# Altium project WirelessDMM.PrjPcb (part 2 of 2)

## Sheet WirelessDMM_AFE.SchDoc: AFE
size 431 x 279 mm; Date: Not shown in title block; ApprovedBy: Not shown in title block; CheckedBy: Not shown in title block; Author: Not shown in title block; CompanyName: Not shown in title block; DrawnBy: Victor Salomon; Engineer: Not shown in title block; Organization: Not shown in title block; Address1: Not shown in title block; Address2: Not shown in title block; Address3: Not shown in title block; Address4: Not shown in title block; DocumentNumber: 3; Revision: Use project parameter SCH_Rev; SheetNumber: 3; SheetTotal: 5; PageSetup: Record=PageOptions¦CenterHorizontal=True¦CenterVertical=True¦PrintScale=1.00¦XCorrection=1.00¦YCorrection=1.00¦PrintKind=0¦BorderSize=5000000¦LeftOffset=0¦BottomOffset=0¦Orientation=2¦PaperLength=1000¦PaperWidth=1000¦Scale=100¦PaperSource=15¦PrintQuality=600¦MediaType=1¦DitherType=10¦PaperKind=Letter¦PrintScaleMode=1
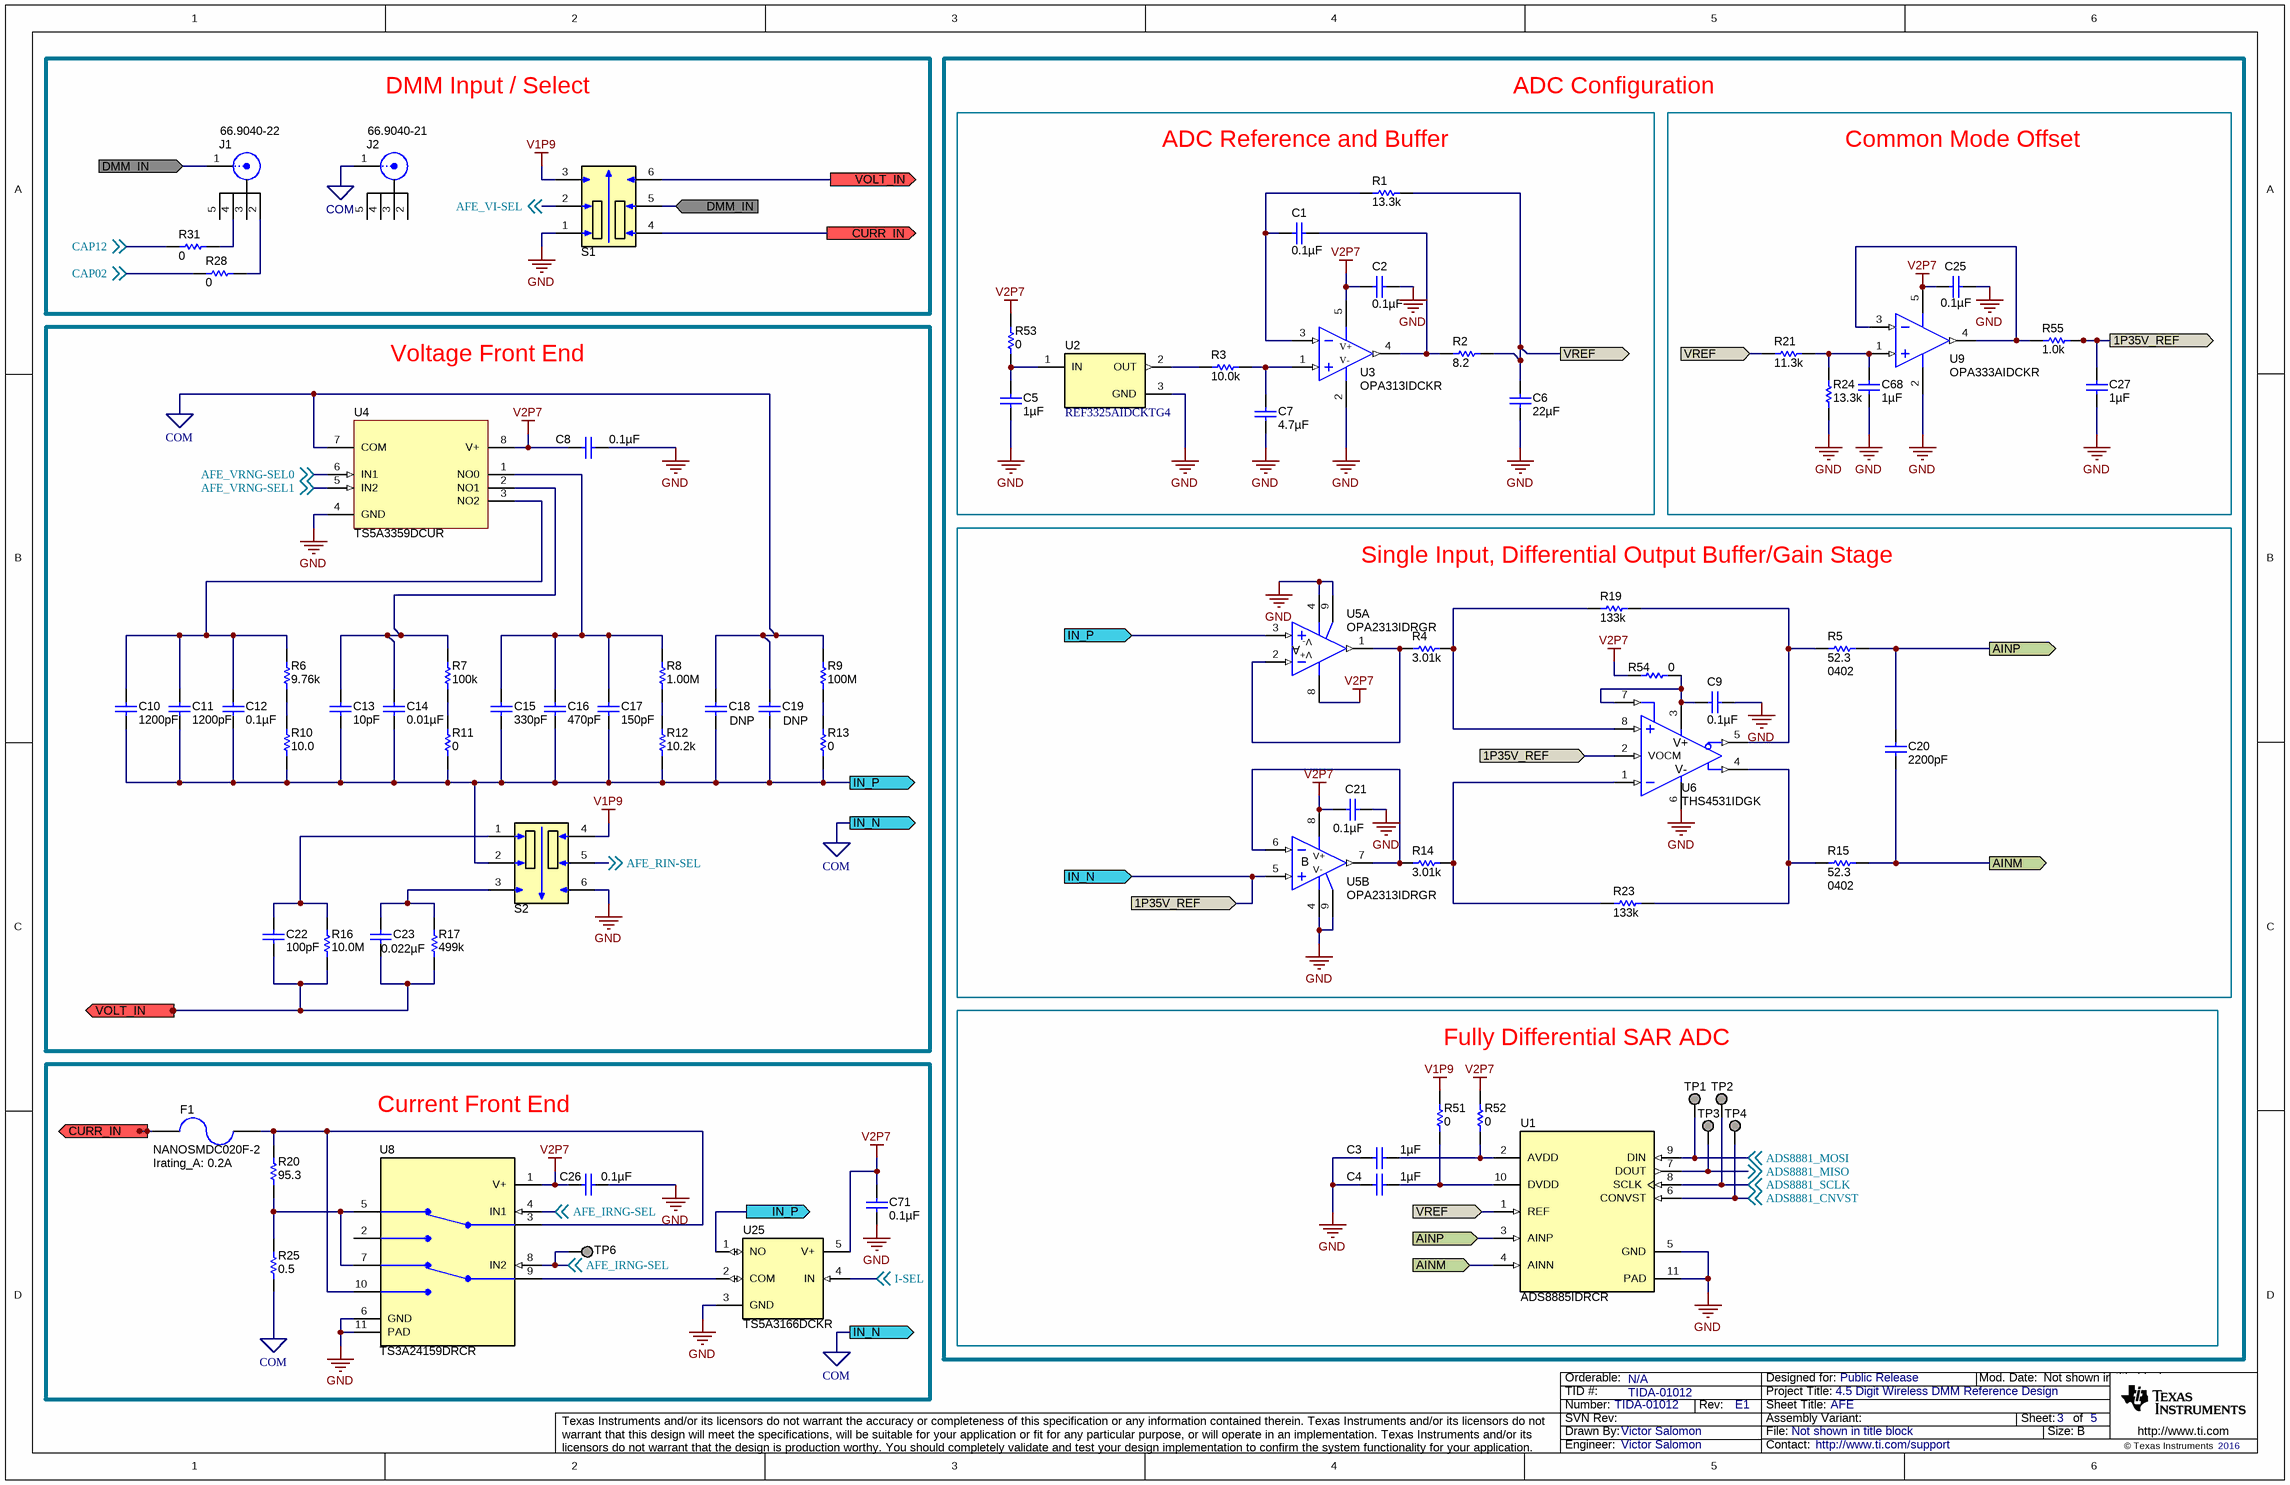
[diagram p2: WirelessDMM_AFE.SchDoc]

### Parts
C1  ValueDisplayed: 0.1µF  [0402S]  (hidden comment: GRM155R71C104JA88D)
C2  ValueDisplayed: 0.1µF  [0201]  (hidden comment: CL03A104KP3NNNC)
C3  ValueDisplayed: 1µF  [0402S]  (hidden comment: GRM155R61A105KE15D)
C4  ValueDisplayed: 1µF  [0402S]  (hidden comment: GRM155R61A105KE15D)
C5  ValueDisplayed: 1µF  [0402S]  (hidden comment: C1005X5R0J105M050BB)
C6  ValueDisplayed: 22µF  [0402S]  (hidden comment: GRM155R60J226ME11D)
C7  ValueDisplayed: 4.7µF  [0603S]  (hidden comment: GRM188R6YA475KE15D)
C8  ValueDisplayed: 0.1µF  [0201]  (hidden comment: CL03A104KP3NNNC)
C9  ValueDisplayed: 0.1µF  [0201]  (hidden comment: CL03A104KP3NNNC)
C10  ValueDisplayed: 1200pF  [0402S]  (hidden comment: C0402C122J5GACTU)
C11  ValueDisplayed: 1200pF  [0402S]  (hidden comment: C0402C122J5GACTU)
C12  ValueDisplayed: 0.1µF  [0603S]  (hidden comment: C0603C104J5RACTU)
C13  ValueDisplayed: 10pF  [0603S]  (hidden comment: C0603C100F5GAC7867)
C14  ValueDisplayed: 0.01µF  [0805_HV1]  (hidden comment: C0805C103F1GACTU)
C15  ValueDisplayed: 330pF  [0402S]  (hidden comment: GRM1555C1H331FA01J)
C16  ValueDisplayed: 470pF  [0805_HV1]  (hidden comment: 08055A471FAT2A)
C17  ValueDisplayed: 150pF  [0402S]  (hidden comment: GRM1555C1H151JA01D)
C18  value DNP  [0402]  (hidden comment: Used in BOM report)
C19  value DNP  [0402]  (hidden comment: Used in BOM report)
C20  ValueDisplayed: 2200pF  [0603S]  (hidden comment: GRM1885C1H222JA01D)
C21  ValueDisplayed: 0.1µF  [0201]  (hidden comment: CL03A104KP3NNNC)
C22  ValueDisplayed: 100pF  [0603S]  (hidden comment: C1608C0G2A101F080AA)
C23  ValueDisplayed: 0.022µF  [0603S]  (hidden comment: C1608X7R2A223K)
C25  ValueDisplayed: 0.1µF  [0201]  (hidden comment: CL03A104KP3NNNC)
C26  ValueDisplayed: 0.1µF  [0201]  (hidden comment: CL03A104KP3NNNC)
C27  ValueDisplayed: 1µF  [0402S]  (hidden comment: C1005X5R0J105M050BB)
C68  ValueDisplayed: 1µF  [0402S]  (hidden comment: C1005X5R0J105M050BB)
C71  ValueDisplayed: 0.1µF  [0201]  (hidden comment: CL03A104KP3NNNC)
F1  NANOSMDC020F-2  Irating_A: 0.2A  [FUSE_NANO02]
J1  66.9040-22  [Multi-Contact_66_9040-22]
J2  66.9040-21  [Multi-Contact_66_9040-21]
R1  ValueDisplayed: 13.3k  [0402S]  (hidden comment: CRCW040213K3FKED)
R2  ValueDisplayed: 8.2  [0402S]  (hidden comment: CRCW04028R20JNED)
R3  ValueDisplayed: 10.0k  [0402S]  (hidden comment: CRCW040210K0FKED)
R4  ValueDisplayed: 3.01k  [0402S]  (hidden comment: CRCW04023K01FKED)
R5  ValueDisplayed: 52.3  PackageReference: 0402  [0402S]  (hidden comment: CRCW040252R3FKED)
R6  ValueDisplayed: 9.76k  [0402S]  (hidden comment: CRCW04029K76FKED)
R7  ValueDisplayed: 100k  [0402S]  (hidden comment: RG1005P-104-B-T5)
R8  ValueDisplayed: 1.00M  [0402S]  (hidden comment: CRCW04021M00FKED)
R9  ValueDisplayed: 100M  [0603S]  (hidden comment: CRCW0603100MJPEAHR)
R10  ValueDisplayed: 10.0  [0402S]  (hidden comment: CRCW040210R0FKED)
R11  ValueDisplayed: 0  [0402S]  (hidden comment: CRCW04020000Z0ED)
R12  ValueDisplayed: 10.2k  [0402S]  (hidden comment: CRCW040210K2FKED)
R13  ValueDisplayed: 0  [0402S]  (hidden comment: CRCW04020000Z0ED)
R14  ValueDisplayed: 3.01k  [0402S]  (hidden comment: CRCW04023K01FKED)
R15  ValueDisplayed: 52.3  PackageReference: 0402  [0402S]  (hidden comment: CRCW040252R3FKED)
R16  ValueDisplayed: 10.0M  [1206L]  (hidden comment: CRHV1206AF10M0FKE5)
R17  ValueDisplayed: 499k  [0402S]  (hidden comment: CRCW0402499KFKED)
R19  ValueDisplayed: 133k  [0402S]  (hidden comment: CRCW0402133KFKED)
R20  ValueDisplayed: 95.3  [2512L]  (hidden comment: CRCW251295R3FKEG)
R21  ValueDisplayed: 11.3k  [0402S]  (hidden comment: CRCW040211K3FKED)
R23  ValueDisplayed: 133k  [0402S]  (hidden comment: CRCW0402133KFKED)
R24  ValueDisplayed: 13.3k  [0402S]  (hidden comment: CRCW040213K3FKED)
R25  ValueDisplayed: 0.5  [0603]  (hidden comment: RL0603FR-070R5L)
R28  ValueDisplayed: 0  [0402S]  (hidden comment: MCR01MZPJ000)
R31  ValueDisplayed: 0  [0402S]  (hidden comment: MCR01MZPJ000)
R51  ValueDisplayed: 0  [0402S]  (hidden comment: MCR01MZPJ000)
R52  ValueDisplayed: 0  [0402S]  (hidden comment: MCR01MZPJ000)
R53  ValueDisplayed: 0  [0402S]  (hidden comment: MCR01MZPJ000)
R54  ValueDisplayed: 0  [0402S]  (hidden comment: MCR01MZPJ000)
R55  ValueDisplayed: 1.0k  [0402S]  (hidden comment: CRCW04021K00JNED)
S1  GS-113-0043  [SW_GS-113-0043]  (value not drawn)
S2  GS-113-0043  [SW_GS-113-0043]  (value not drawn)
TP1  TESTPOINT  [TP_SM_1MM]  (value not drawn)  (no BOM)
TP2  TESTPOINT  [TP_SM_1MM]  (value not drawn)  (no BOM)
TP3  TESTPOINT  [TP_SM_1MM]  (value not drawn)  (no BOM)
TP4  TESTPOINT  [TP_SM_1MM]  (value not drawn)  (no BOM)
TP6  TESTPOINT  [TP_SM_1MM]  (value not drawn)  (no BOM)
U1  ADS8885IDRCR  [DRC0010D]
U2  REF3325AIDCKTG4  [DCK0003A_N]
U3  OPA313IDCKR  [DCK0005A_N]
U4  TS5A3359DCUR  [DCU0008A_N]
U5  OPA2313IDRGR  [DRG0008A]  (parts A,B of 2)
U6  THS4531IDGK  [DGK0008A_N]
U8  TS3A24159DRCR  [DRC0010J]
U9  OPA333AIDCKR  [DCK0005A_N]
U25  TS5A3166DCKR  [DCK0005A_N]

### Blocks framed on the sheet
DMM Input / Select: J1 J2 R28 R31 S1
ADC Reference and Buffer: C1 C2 C5-C7 R1-R3 R53 U2 U3
Common Mode Offset: C25 C27 C68 R21 R24 R55 U9
Voltage Front End: C8 C10-C19 C22 C23 R6-R13 R16 R17 S2 U4
Single Input, Differential Output Buffer/Gain Stage: C9 C20 C21 R4 R5 R14 R15 R19 R23 R54 U5 U6
Fully Differential SAR ADC: C3 C4 R51 R52 TP1-TP4 U1
Current Front End: C26 C71 F1 R20 R25 TP6 U8 U25

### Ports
1P35V_REF (in), 1P35V_REF (out), AINM (in), AINM (out), AINP (in), AINP (out), CURR_IN (in), CURR_IN (out), DMM_IN (in), IN_N (in), IN_N (out), IN_P (in), IN_P (out), VOLT_IN (in), VOLT_IN (out), VREF (in), VREF (out)

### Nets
COM: C18.2 C19.2 C27.1 J2.1 R9.2 R25.1 R55.1 U4.7(COM) U5.5(IN+) U6.2(VOCM) ; port 1P35V_REF, port IN_N
GND: C2.1 C3.1 C4.1 C5.2 C6.2 C7.2 C8.1 C9.1 C21.1 C25.1 C26.1 C27.2 C68.2 C71.1 R24.1 S1.1 S2.6 U1.5(GND) U1.11(PAD) U2.3(GND) U3.2(V-) U4.4(GND) U5.4(V-) U5.9(PAD) U6.6(VS-) U8.6(GND) U8.11(PAD) U9.2(V-) U25.3(GND)
V1P9: R51.2 S1.3 S2.4
V2P7: C2.2 C8.2 C21.2 C25.2 C26.2 C71.2 R52.2 R53.2 R54.2 U3.5(V+) U4.8(V+) U5.8(V+) U8.1(V+) U9.5(V+) U25.5(V+)
ADS8881_CNVST: TP4.1 U1.6(CONVST) ; off-sheet ADS8881_CNVST
ADS8881_MISO: TP3.1 U1.7(DOUT) ; off-sheet ADS8881_MISO
ADS8881_MOSI: TP1.1 U1.9(DIN) ; off-sheet ADS8881_MOSI
ADS8881_SCLK: TP2.1 U1.8(SCLK) ; off-sheet ADS8881_SCLK
AFE_IRNG-SEL: TP6.1 U8.4(IN1) U8.8(IN2) ; off-sheet AFE_IRNG-SEL
AFE_RIN-SEL: S2.5(C) ; off-sheet AFE_RIN-SEL
AFE_VI-SEL: S1.2(C) ; off-sheet AFE_VI-SEL
AFE_VRNG-SEL0: U4.6(IN1) ; off-sheet AFE_VRNG-SEL0
AFE_VRNG-SEL1: U4.5(IN2) ; off-sheet AFE_VRNG-SEL1
AINM: C20.1 R15.2 U1.4(AINN) ; port AINM
AINP: C20.2 R5.2 U1.3(AINP) ; port AINP
CAP02: R28.2 ; off-sheet CAP02
CAP12: R31.2 ; off-sheet CAP12
CURR_IN: F1.1 S1.4 ; port CURR_IN
DMM_IN: J1.1 S1.5(C) ; port DMM_IN
I-SEL: U25.4(IN) ; off-sheet I-SEL
IN_P: C10.1 C11.1 C12.1 C13.1 C14.1 C15.1 C16.1 C17.1 C18.1 C19.1 R10.1 R11.1 R12.1 R13.1 S2.2(C) U5.3(IN+) U25.1(NO) ; port IN_P
VOLT_IN: C22.1 C23.2 R16.1 R17.2 S1.6 ; port VOLT_IN
VREF: C6.1 R1.2 R2.2 R21.2 U1.1(REF) ; port VREF
NetC1_1: C1.1 R1.1 U3.3(IN-)
NetC1_2: C1.2 R2.1 U3.4(OUT)
NetC3_2: C3.2 R52.1 U1.2(AVDD)
NetC4_2: C4.2 R51.1 U1.10(DVDD)
NetC5_1: C5.1 R53.1 U2.1(IN)
NetC7_1: C7.1 R3.2 U3.1(IN+)
NetC9_2: C9.2 R54.1 U6.3(VS+) U6.7(~{PD})
NetC10_2: C10.2 C11.2 C12.2 R6.2 U4.3(NO2)
NetC13_2: C13.2 C14.2 R7.2 U4.2(NO1)
NetC15_2: C15.2 C16.2 C17.2 R8.2 U4.1(NO0)
NetC22_2: C22.2 R16.2 S2.1
NetC23_1: C23.1 R17.1 S2.3
NetC68_1: C68.1 R21.1 R24.2 U9.1(IN+)
NetF1_2: F1.2 R20.2 U8.3(COM1) U8.10(NO2)
NetJ1_2: J1.2 R28.1
NetJ1_4: J1.4 R31.1
NetR3_1: R3.1 U2.2(OUT)
NetR4_1: R4.1 U5.1(OUT) U5.2(IN-)
NetR4_2: R4.2 R19.2 U6.8(VIN+)
NetR5_1: R5.1 R19.1 U6.5(VOUT-)
NetR6_1: R6.1 R10.2
NetR7_1: R7.1 R11.2
NetR8_1: R8.1 R12.2
NetR9_1: R9.1 R13.2
NetR14_1: R14.1 R23.1 U6.1(VIN-)
NetR14_2: R14.2 U5.6(IN-) U5.7(OUT)
NetR15_1: R15.1 R23.2 U6.4(VOUT+)
NetR20_1: R20.1 R25.2 U8.5(NC1) U8.7(NC2)
NetR55_2: R55.2 U9.3(IN-) U9.4(OUT)
NetU8_9: U8.9(COM2) U25.2(COM)

Not connected (* = marked no-connect by the designer): J1 3 5; J2 2 3 4 5; U8 2(NO1)

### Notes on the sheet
- ADC Configuration

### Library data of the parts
C1 = GRM155R71C104JA88D: CAP, CERM, 0.1 µF, 16 V, +/- 5%, X7R, 0402; Manufacturer: MuRata; Polarized: N; CompType: Capacitor; Value: 0.1uF; U/M: EA; Cap_F: 0.0000001; Tolerance_%: 5; Value1: Unknown; VDC_V: 16; Value2: 16V; TaMin_C: -55; TaMax_C: 125; Cap_Case: 0402; SizeArea_mm2: 0.5; SizeAreaWB_mm2: 3; SizeX_mm: 1; SizeZ_mm: 0.6; AEC Category: Q200
C2 C8 C9 C21 C25 C26 C71 = CL03A104KP3NNNC: CAP, CERM, 0.1 µF, 10 V, +/- 10%, X5R, 0201; Manufacturer: Samsung Electro-Mechanics; Polarized: N; CompType: Capacitor; Value: 0.1uF; U/M: EA; Cap_F: 0.0000001; Tolerance_%: 10; Value1: Unknown; Value2: 10V; TaMin_C: -55; TaMax_C: 85; AEC Category: Q200
C3 C4 = GRM155R61A105KE15D: CAP, CERM, 1 µF, 10 V, +/- 10%, X5R, 0402; Manufacturer: MuRata; Polarized: N; CompType: Capacitor; Value: 1uF; U/M: EA; Cap_F: 0.000001; Tolerance_%: 10; Value1: Unknown; Value2: 10V; TaMin_C: -55; TaMax_C: 85; Cap_Case: 0402; AEC Category: Q200
C5 C27 C68 = C1005X5R0J105M050BB: CAP, CERM, 1 µF, 6.3 V, +/- 20%, X5R, 0402; Manufacturer: TDK; Polarized: N; CompType: Capacitor; Value: 1uF; U/M: EA; Cap_F: 0.000001; Tolerance_%: 20; ESR_ohm: 0.0079; Value1: 0.0079 ohm; VDC_V: 6.3; Value2: 6.3V; TaMin_C: -55; TaMax_C: 85; Cap_Case: 0402; AEC Category: Q200
C6 = GRM155R60J226ME11D: CAP, CERM, 22 µF, 6.3 V, +/- 20%, X5R, 0402; Manufacturer: MuRata; Polarized: N; CompType: Capacitor; Value: 22uF; U/M: EA; Cap_F: 0.000022; Tolerance_%: 20; Value1: Unknown; VDC_V: 6.3; Value2: 6.3V; TaMin_C: -55; TaMax_C: 85; Cap_Case: 0402; AEC Category: Q200
C7 = GRM188R6YA475KE15D: CAP, CERM, 4.7 µF, 35 V, +/- 10%, X5R, 0603; Manufacturer: MuRata; Polarized: N; CompType: Capacitor; Value: 4.7uF; U/M: EA; Cap_F: 0.0000047; Tolerance_%: 10; Value1: Unknown; VDC_V: 35; Value2: 35V; TaMin_C: -55; TaMax_C: 85; Cap_Case: 0603; AEC Category: Q200; SizeArea_mm2: 1.28; SizeAreaWB_mm2: 4.68; SizeX_mm: 1.6; SizeY_mm: 0.8; SizeZ_mm: 1
C10 C11 = C0402C122J5GACTU: CAP, CERM, 1200 pF, 50 V, +/- 5%, C0G/NP0, 0402; Manufacturer: Kemet; Polarized: N; CompType: Capacitor; Value: 1200pF; U/M: EA; Cap_F: 0.0000000012; Tolerance_%: 5; Value1: Unknown; VDC_V: 50; Value2: 50V; TaMin_C: -55; TaMax_C: 125; Cap_Case: 0402; AEC Category: Q200; SizeArea_mm2: 0.5; SizeAreaWB_mm2: 3; SizeX_mm: 1; SizeZ_mm: 0.6
C12 = C0603C104J5RACTU: CAP, CERM, 0.1 µF, 50 V, +/- 5%, X7R, 0603; Manufacturer: Kemet; Polarized: N; CompType: Capacitor; Value: 0.1uF; U/M: EA; Cap_F: 0.0000001; Tolerance_%: 5; Value1: Unknown; VDC_V: 50; Value2: 50V; TaMin_C: -55; TaMax_C: 125; Cap_Case: 0603; AEC Category: Q200; SizeArea_mm2: 1.28; SizeAreaWB_mm2: 4.68; SizeX_mm: 1.6; SizeY_mm: 0.8; SizeZ_mm: 1
C13 = C0603C100F5GAC7867: CAP, CERM, 10 pF, 50 V, +/- 1%, C0G/NP0, 0603; Manufacturer: Kemet; Polarized: N; CompType: Capacitor; Value: 10pF; U/M: EA; Cap_F: 0.00000000001; Tolerance_%: 1; Value1: Unknown; VDC_V: 50; Value2: 50V; TaMin_C: -55; TaMax_C: 125; Cap_Case: 0603; AEC Category: Q200
C14 = C0805C103F1GACTU: CAP, CERM, 0.01 µF, 100 V, +/- 1%, C0G/NP0, 0805; Manufacturer: Kemet; Polarized: N; CompType: Capacitor; Value: 0.01uF; U/M: EA; Cap_F: 0.00000001; Tolerance_%: 1; Value1: Unknown; VDC_V: 100; Value2: 100V; TaMin_C: -55; TaMax_C: 125; Cap_Case: 0805; AEC Category: Q200
C15 = GRM1555C1H331FA01J: CAP, CERM, 330 pF, 50 V, +/- 1%, C0G/NP0, 0402; Manufacturer: MuRata; Polarized: N; CompType: Capacitor; Value: 330pF; U/M: EA; Cap_F: 0.00000000033; Tolerance_%: 1; Value1: Unknown; VDC_V: 50; Value2: 50V; TaMin_C: -55; TaMax_C: 125; Cap_Case: 0402; AEC Category: Q200
C16 = 08055A471FAT2A: CAP, CERM, 470 pF, 50 V, +/- 1%, C0G/NP0, 0805; Manufacturer: AVX; Polarized: N; CompType: Capacitor; Value: 470pF; U/M: EA; Cap_F: 0.00000000047; Tolerance_%: 1; ESR_ohm: 0.159; Value1: 0.159 ohm; VDC_V: 50; Value2: 50V; TaMin_C: -55; TaMax_C: 125; Cap_Case: 0805; AEC Category: Q200
C17 = GRM1555C1H151JA01D: CAP, CERM, 150 pF, 50 V, +/- 5%, C0G/NP0, 0402; Manufacturer: MuRata; Polarized: N; CompType: Capacitor; Value: 150pF; U/M: EA; Cap_F: 0.00000000015; Tolerance_%: 5; Value1: Unknown; VDC_V: 50; Value2: 50V; TaMin_C: -55; TaMax_C: 125; Cap_Case: 0402; AEC Category: Q200
C18 C19 = Capacitor: Cap, 0402 footprint placeholder; Polarized: N; U/M: EA
C20 = GRM1885C1H222JA01D: CAP, CERM, 2200 pF, 50 V, +/- 5%, C0G/NP0, 0603; Manufacturer: MuRata; Polarized: N; CompType: Capacitor; Value: 2200pF; U/M: EA; Cap_F: 0.0000000022; Tolerance_%: 5; Value1: Unknown; VDC_V: 50; Value2: 50V; TaMin_C: -55; TaMax_C: 125; Cap_Case: 0603; AEC Category: Q200; SizeArea_mm2: 1.28; SizeAreaWB_mm2: 4.68; SizeX_mm: 1.6; SizeY_mm: 0.8; SizeZ_mm: 1
C22 = C1608C0G2A101F080AA: CAP, CERM, 100 pF, 100 V, +/- 1%, C0G/NP0, 0603; Manufacturer: TDK; Polarized: N; CompType: Capacitor; Value: 100pF; U/M: EA; Cap_F: 0.0000000001; Tolerance_%: 1; Value1: Unknown; VDC_V: 100; Value2: 100V; TaMin_C: -55; TaMax_C: 125; Cap_Case: 0603; AEC Category: Q200
C23 = C1608X7R2A223K: CAP, CERM, 0.022 µF, 100 V, +/- 10%, X7R, 0603; Manufacturer: TDK; Polarized: N; CompType: Capacitor; Value: 0.022uF; U/M: EA; Cap_F: 0.000000022; Tolerance_%: 10; ESR_ohm: 0.037; Value1: 0.037 ohm; VDC_V: 100; Value2: 100V; TaMin_C: -55; TaMax_C: 125; Cap_Case: 0603; AEC Category: Q200
F1 = NANOSMDC020F-2: Fuse, Resettable, 0.2 A, 24 VDC, SMD; Manufacturer: TE Connectivity; VDC_V: 24; Rtyp_Ohm: 1.875; SymbolCreator: a0412235
J1 = 66.9040-22: MAH561 Connector, XELW-4, Red, THD; Manufacturer: Multi-Contact; SymbolCreator: a0799628
J2 = 66.9040-21: MAH561 Connector, XELW-4, Black, THD; Manufacturer: Multi-Contact; SymbolCreator: a0799628
R1 = CRCW040213K3FKED: RES, 13.3 k, 1%, 0.063 W, 0402; Manufacturer: Vishay-Dale; CompType: Resistor; Value: 13.3k; Res_ohm: 13300; Value_Code: 13k3; Tolerance_%: 1; Power_W: 0.063; Value2: 0.063W; VDC_V: 50; TempCo: 100 ppm/C; EIA_Code: E96; U/M: EA; AEC Category: Q200; SizeArea_mm2: 0.5; SizeZ_mm: 0.6
R2 = CRCW04028R20JNED: RES, 8.2, 5%, 0.063 W, 0402; Manufacturer: Vishay-Dale; CompType: Resistor; Value: 8.2; Value_Code: 8R20; Tolerance_%: 5; Power_W: 0.063; Value2: 0.063W; VDC_V: 50; TempCo: 200 ppm/C; EIA_Code: E24; U/M: EA; AEC Category: Q200; SizeArea_mm2: 0.5; SizeX_mm: 1; SizeZ_mm: 0.6
R3 = CRCW040210K0FKED: RES, 10.0 k, 1%, 0.063 W, 0402; Manufacturer: Vishay-Dale; CompType: Resistor; Value: 10.0k; Res_ohm: 10000; Value_Code: 10k0; Tolerance_%: 1; Power_W: 0.063; Value2: 0.063W; VDC_V: 50; TempCo: 100 ppm/C; EIA_Code: E96; U/M: EA; AEC Category: Q200
R4 R14 = CRCW04023K01FKED: RES, 3.01 k, 1%, 0.063 W, 0402; Manufacturer: Vishay-Dale; CompType: Resistor; Value: 3.01k; Res_ohm: 3010; Value_Code: 3k01; Tolerance_%: 1; Power_W: 0.063; Value2: 0.063W; VDC_V: 50; TempCo: 100 ppm/C; EIA_Code: E96; U/M: EA; AEC Category: Q200; SizeArea_mm2: 0.5; SizeZ_mm: 0.6
R5 R15 = CRCW040252R3FKED: RES, 52.3, 1%, 0.063 W, 0402; Manufacturer: Vishay-Dale; CompType: Resistor; Value: 52.3; Value_Code: 52R3; Tolerance_%: 1; Power_W: 0.063; Value2: 0.063W; VDC_V: 50; TempCo: 100 ppm/C; EIA_Code: E96; U/M: EA; AEC Category: Q200
R6 = CRCW04029K76FKED: RES, 9.76 k, 1%, 0.063 W, 0402; Manufacturer: Vishay-Dale; CompType: Resistor; Value: 9.76k; Res_ohm: 9760; Value_Code: 9k76; Tolerance_%: 1; Power_W: 0.063; Value2: 0.063W; VDC_V: 50; TempCo: 100 ppm/C; EIA_Code: E96; U/M: EA; AEC Category: Q200
R7 = RG1005P-104-B-T5: RES, 100 k, 0.1%, 0.063 W, 0402; Manufacturer: Susumu Co Ltd; CompType: Resistor; Value: 100k; Res_ohm: 100000; Tolerance_%: 0.1; Power_W: 0.063; Value2: 0.063W; TempCo: 25 ppm/C; EIA_Code: E192; U/M: EA; AEC Category: Q200
R8 = CRCW04021M00FKED: RES, 1.00 M, 1%, 0.063 W, 0402; Manufacturer: Vishay-Dale; CompType: Resistor; Value: 1.00Meg; Res_ohm: 1000000; Value_Code: 1M00; Tolerance_%: 1; Power_W: 0.063; Value2: 0.063W; VDC_V: 50; TempCo: 100 ppm/C; EIA_Code: E96; U/M: EA; AEC Category: Q200
R9 = CRCW0603100MJPEAHR: RES, 100 M, 5%, 0.1 W, 0603; Manufacturer: Vishay-Dale; CompType: Resistor; Value: 100Meg; Res_ohm: 100000000; Tolerance_%: 5; Power_W: 0.1; Value2: 0.1W; VDC_V: 75; TempCo: 500 ppm/C; U/M: EA; AEC Category: Q200
R10 = CRCW040210R0FKED: RES, 10.0, 1%, 0.063 W, 0402; Manufacturer: Vishay-Dale; CompType: Resistor; Value: 10.0; Res_ohm: 10; Value_Code: 10R0; Tolerance_%: 1; Power_W: 0.063; Value2: 0.063W; VDC_V: 50; TempCo: 100 ppm/C; EIA_Code: E96; U/M: EA; AEC Category: Q200
R11 R13 = CRCW04020000Z0ED: RES, 0, 5%, 0.063 W, 0402; Manufacturer: Vishay-Dale; CompType: Resistor; Value: 0; Value_Code: 0000; Tolerance_%: 5; Power_W: 0.063; Value2: 0.063W; VDC_V: 50; TempCo: 200 ppm/C; EIA_Code: E24; U/M: EA; AEC Category: Q200
R12 = CRCW040210K2FKED: RES, 10.2 k, 1%, 0.063 W, 0402; Manufacturer: Vishay-Dale; CompType: Resistor; Value: 10.2k; Res_ohm: 10200; Value_Code: 10k2; Tolerance_%: 1; Power_W: 0.063; Value2: 0.063W; VDC_V: 50; TempCo: 100 ppm/C; EIA_Code: E96; U/M: EA; AEC Category: Q200
R16 = CRHV1206AF10M0FKE5: RES, 10.0 M, 1%, 0.3 W, 1206; Manufacturer: Vishay-Dale; CompType: Resistor; Value: 10.0Meg; Res_ohm: 10000000; Value_Code: 10M0; Tolerance_%: 1; Power_W: 0.3; Value2: 0.3W; VDC_V: 1500; TempCo: 100 ppm/C; EIA_Code: E96; U/M: EA; AEC Category: Q200; AEC Qualified: N
R17 = CRCW0402499KFKED: RES, 499 k, 1%, 0.063 W, 0402; Manufacturer: Vishay-Dale; CompType: Resistor; Value: 499k; Res_ohm: 499000; Tolerance_%: 1; Power_W: 0.063; Value2: 0.063W; VDC_V: 50; TempCo: 100 ppm/C; EIA_Code: E96; U/M: EA; AEC Category: Q200
R19 R23 = CRCW0402133KFKED: RES, 133 k, 1%, 0.063 W, 0402; Manufacturer: Vishay-Dale; CompType: Resistor; Value: 133k; Res_ohm: 133000; Tolerance_%: 1; Power_W: 0.063; Value2: 0.063W; VDC_V: 50; TempCo: 100 ppm/C; EIA_Code: E96; U/M: EA; AEC Category: Q200; SizeArea_mm2: 0.5; SizeZ_mm: 0.6
R20 = CRCW251295R3FKEG: RES, 95.3, 1%, 1 W, 2512; Manufacturer: Vishay-Dale; CompType: Resistor; Value: 95.3; Value_Code: 95R3; Tolerance_%: 1; Value2: 1W; VDC_V: 500; TempCo: 100 ppm/C; EIA_Code: E96; U/M: EA; AEC Category: Q200
R21 = CRCW040211K3FKED: RES, 11.3 k, 1%, 0.063 W, 0402; Manufacturer: Vishay-Dale; CompType: Resistor; Value: 11.3k; Res_ohm: 11300; Value_Code: 11k3; Tolerance_%: 1; Power_W: 0.063; Value2: 0.063W; VDC_V: 50; TempCo: 100 ppm/C; EIA_Code: E96; U/M: EA; AEC Category: Q200
R24 = CRCW040213K3FKED: RES, 13.3 k, 1%, 0.063 W, 0402; Manufacturer: Vishay-Dale; CompType: Resistor; Value: 13.3k; Res_ohm: 13300; Value_Code: 13k3; Tolerance_%: 1; Power_W: 0.063; Value2: 0.063W; VDC_V: 50; TempCo: 100 ppm/C; EIA_Code: E96; U/M: EA; AEC Category: Q200
R25 = RL0603FR-070R5L: RES, 0.5, 1%, 0.1 W, 0603; Manufacturer: Yageo America; CompType: Resistor; Value: 0.5; Value_Code: R500; Tolerance_%: 1; Power_W: 0.1; Value2: 0.1W; TempCo: 800 ppm/C; U/M: EA; AEC Category: Q200
R28 R31 R51-R54 = MCR01MZPJ000: RES, 0, 5%, 0.063 W, 0402; Manufacturer: Rohm; CompType: Resistor; Value: 0; Value_Code: 0000; Tolerance_%: 5; Power_W: 0.063; Value2: 0.063W; VDC_V: 50; TempCo: 500 ppm/C; EIA_Code: E24; U/M: EA; AEC Category: Q200
R55 = CRCW04021K00JNED: RES, 1.0 k, 5%, 0.063 W, 0402; Manufacturer: Vishay-Dale; CompType: Resistor; Value: 1.0k; Res_ohm: 1000; Value_Code: 1k00; Tolerance_%: 5; Power_W: 0.063; Value2: 0.063W; VDC_V: 50; TempCo: 200 ppm/C; EIA_Code: E24; U/M: EA; AEC Category: Q200
S1 S2 = GS-113-0043: Switch, Slide, DPDT, On-On, 0.5 A, 125 V, TH; Manufacturer: CW Industries; SymbolCreator: x0208325; VDC_V: 125; PositionCount: 2; CurrentRating_mA: 500
TP1-TP4 TP6 = TP_SM_1MM: 1mm Test Point, SMT; Manufacturer: Any
U1 = ADS8885IDRCR: 18-Bit, 400-kSPS, Serial Interface, microPower, Miniature, True-Differential Input, SAR Analog-to-Digital Converter, DRC0010D; Alternate PartNumber: ADS8885IDRCT; Manufacturer: Texas Instruments; SymbolCreator: Altium; SizeArea_mm2: 9; SizeAreaWB_mm2: 16; SizeX_mm: 3; SizeZ_mm: 1; CompType: IC; U/M: EA
U2 = REF3325AIDCKTG4: 30 ppm / degC Drift, 3.9 uA Voltage Reference, -40 to 125 degC, 3-pin SC70 (DCK), Green (RoHS & no Sb/Br); Manufacturer: Texas Instruments; Alternate PartNumber: Equivalent; Initial Accuracy @ 25/deg C(%): 0.15; Iout/Iz(Max)(mA): 5; Rating: Catalog; SubFamily: Series Voltage Reference; Temp Coeff(Max)(ppm/ degree C): 30; Temp Coeff(Typ)(ppm/ degree C): 8; VI(Max)(V): 5.5; VI(Min)(V): 2.66; VO(V): 2.5
U3 = OPA313IDCKR: 1-MHz, Micro-Power, Low-Noise, RRIO,1.8-V CMOS OPERATIONAL AMPLIFIER Precision Value Line Series, DCK0005A; Alternate PartNumber: OPA313IDCKT; Manufacturer: Texas Instruments; CompType: IC; Sim Note: Shutdown not modeled; U/M: EA
U4 = TS5A3359DCUR: 1-Ohm SP3T ANALOG SWITCH 5-V/3.3-V SINGLE-CHANNEL 3:1 MULTIPLEXER/DEMULTIPLEXER, DCU0008A; Alternate PartNumber: TS5A3359DCUT; Manufacturer: Texas Instruments; SymbolCreator: Altium; CompType: IC; U/M: EA
U5 = OPA2313IDRGR: 1-MHz, Micro-Power, Low-Noise, RRIO,1.8-V CMOS OPERATIONAL AMPLIFIER Precision Value Line Series, DRG0008A; Alternate PartNumber: OPA2313IDRGT; Manufacturer: Texas Instruments; SymbolCreator: a0411947; SizeArea_mm2: 9; SizeAreaWB_mm2: 16; SizeX_mm: 3; SizeZ_mm: 0.8; CompType: IC; U/M: EA
U6 = THS4531IDGK: Ultra Low Power, Rail-to-Rail Output, Fully-Differential Amplifier, DGK0008A; Manufacturer: Texas Instruments; SymbolCreator: a0411947; CompType: IC; U/M: EA
U8 = TS3A24159DRCR: 0.3-ohm 2-Channel SPDT Bidirectional Analog Switch Dual-Channel 2:1 Multiplexer and Demultiplexer, DRC0010J; Manufacturer: Texas Instruments; SymbolCreator: Altium; SizeArea_mm2: 9; SizeAreaWB_mm2: 16; SizeX_mm: 3; SizeZ_mm: 1; CompType: IC; U/M: EA
U9 = OPA333AIDCKR: 17 uA, MicroPower, Precision, Zero Drift CMOS Operational Amplifier, 1.8 to 5.5 V, -40 to 125 degC, 5-pin SOT23 (DCK0005A), Green (RoHS & no Sb/Br); Alternate PartNumber: Equivalent; Manufacturer: Texas Instruments; CMRR(Min)(dB): 106; IIB(Max)(pA): 200; Iq per channel(Max)(mA): 0.025; Number of Channels: 1; Offset Drift(Typ)(uV/C): 0.02; Slew Rate(Typ)(V/us): 0.16; Sub Family: Low Offset Voltage Amplifier (<=500uV), Low Power Amp (<=500uA), Low Supply Voltage Amplifier (<=2.7V), Precision Amplifier, Zero Drift Precision Amplifier; Total Supply Voltage(Max)(+5V is 5, +/-5V is 10): 5.5; Total Supply Voltage(Min)(+5V is 5, +/-5V is 10): 1.8; Vio (25C)(Max)(mV): 0.01
U25 = TS5A3166DCKR: 0.9-Ohm SPST ANALOG SWITCH, DCK0005A; Manufacturer: Texas Instruments; SymbolCreator: x0208325; SizeArea_mm2: 4.2; SizeX_mm: 2.1; SizeY_mm: 2; SizeZ_mm: 1.1; CompType: IC; U/M: EA

## Sheet WirelessDMM_Hardware.SchDoc: Hardware
size 431 x 279 mm; Date: Not shown in title block; ApprovedBy: Not shown in title block; CheckedBy: Not shown in title block; Author: Not shown in title block; CompanyName: Not shown in title block; DrawnBy: Victor Salomon; Engineer: Not shown in title block; Organization: Not shown in title block; Address1: Not shown in title block; Address2: Not shown in title block; Address3: Not shown in title block; Address4: Not shown in title block; DocumentNumber: 4; Revision: Use project parameter SCH_Rev; SheetNumber: 4; SheetTotal: 4; PageSetup: Record=PageOptions¦CenterHorizontal=True¦CenterVertical=True¦PrintScale=1.00¦XCorrection=1.00¦YCorrection=1.00¦PrintKind=0¦BorderSize=5000000¦LeftOffset=0¦BottomOffset=0¦Orientation=2¦PaperLength=1000¦PaperWidth=1000¦Scale=100¦PaperSource=15¦PrintQuality=600¦MediaType=1¦DitherType=10¦PaperKind=Letter¦PrintScaleMode=1
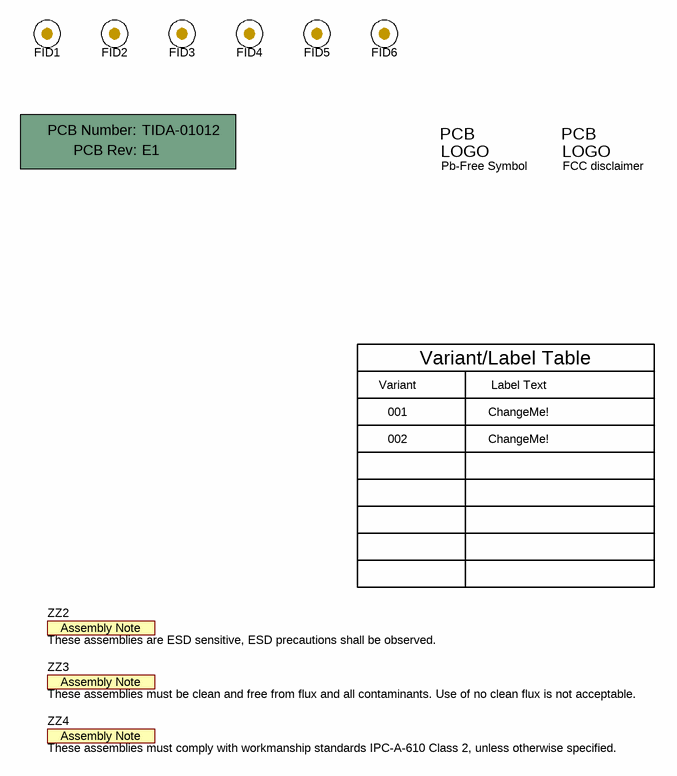
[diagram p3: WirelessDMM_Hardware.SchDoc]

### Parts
!PCB  Printed Circuit Board  (value not drawn)  (mechanical)
FID1  Fiducial  [Fiducial10-20]  (value not drawn)
FID2  Fiducial  [Fiducial10-20]  (value not drawn)
FID3  Fiducial  [Fiducial10-20]  (value not drawn)
FID4  Fiducial  [Fiducial10-20]  (value not drawn)
FID5  Fiducial  [Fiducial10-20]  (value not drawn)
FID6  Fiducial  [Fiducial10-20]  (value not drawn)
Logo2  Pb-Free Symbol  [Pb-Free_Overlay_Small]  (no BOM)
Logo3  FCC disclaimer  [FCC_disclaimer]  (no BOM)
ZZ2  These assemblies are ESD sensitive, ESD precautions shall be observed.  [AssemblyNote]  (no BOM)
ZZ3  These assemblies must be clean and free from flux and all contaminants. Use of no clean flux is not acceptable.  [AssemblyNote]  (no BOM)
ZZ4  These assemblies must comply with workmanship standards IPC-A-610 Class 2, unless otherwise specified.  [AssemblyNote]  (no BOM)

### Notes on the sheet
- Variant
- Variant/Label Table
- Label Text
- 001
- 002
- ChangeMe!

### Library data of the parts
!PCB = PCB: Manufacturer: Any; PartNumber: TIDA-01012; SymbolCreator: a0412235
FID1-FID6 = Fiducial: Fiducial mark.  There is nothing to buy or mount.; SymbolCreator: codlsc
Logo2 = Pb-Free: SymbolCreator: a0412235
Logo3 = FCC_disclaimer: SymbolCreator: codlsc
ZZ2-ZZ4 = AssemblyNote: SymbolCreator: codlsc

## Sheet WirelessDMM_Block_Diagram.SchDoc: Block Diagram
size 431 x 279 mm; Date: Not shown in title block; ApprovedBy: Not shown in title block; CheckedBy: Not shown in title block; Author: Not shown in title block; CompanyName: Not shown in title block; Engineer: Not shown in title block; Organization: Not shown in title block; Address1: Not shown in title block; Address2: Not shown in title block; Address3: Not shown in title block; Address4: Not shown in title block; DocumentNumber: 1; Revision: Use project parameter SCH_Rev; SheetNumber: 1; SheetTotal: 5; PageSetup: Record=PageOptions¦CenterHorizontal=True¦CenterVertical=True¦PrintScale=1.00¦XCorrection=1.00¦YCorrection=1.00¦PrintKind=0¦BorderSize=5000000¦LeftOffset=0¦BottomOffset=0¦Orientation=2¦PaperLength=1000¦PaperWidth=1000¦Scale=100¦PaperSource=15¦PrintQuality=600¦MediaType=1¦DitherType=10¦PaperKind=Letter¦PrintScaleMode=1
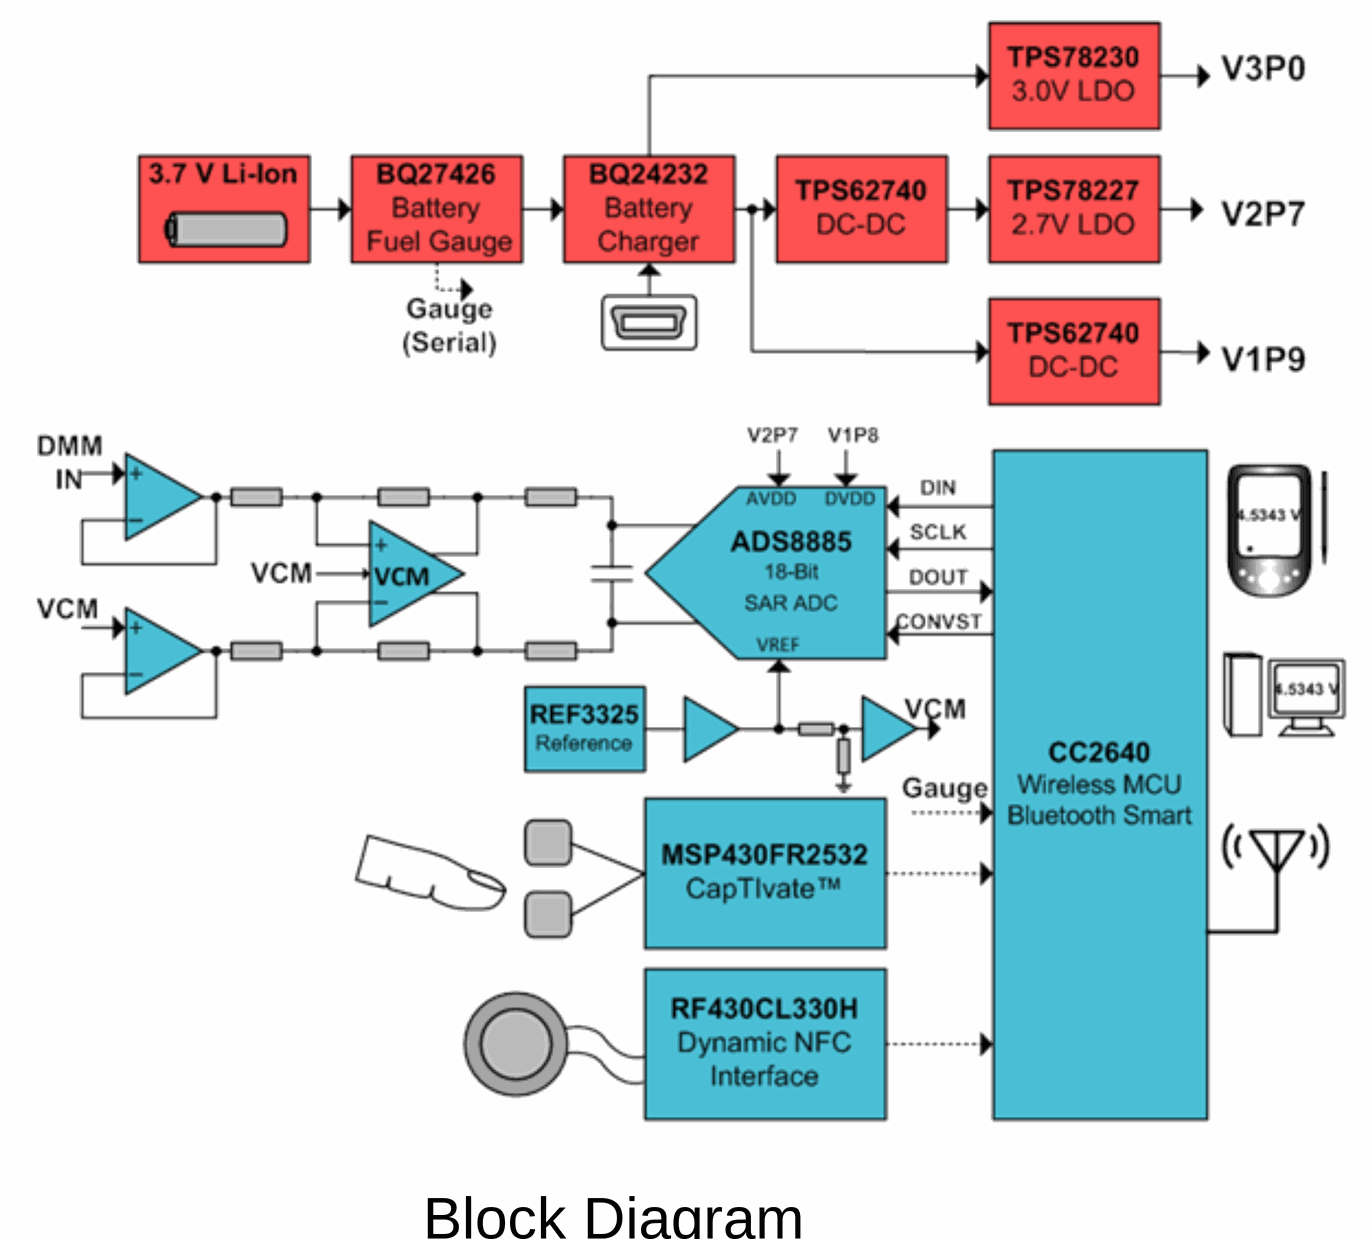
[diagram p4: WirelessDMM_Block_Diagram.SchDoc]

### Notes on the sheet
- Block Diagram

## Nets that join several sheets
GND: WirelessDMM_PWR (52 pins), WirelessDMM_MCU (66 pins), WirelessDMM_AFE (29 pins)
V1P9: WirelessDMM_PWR (6 pins), WirelessDMM_MCU (15 pins), WirelessDMM_AFE (R51.2 S1.3 S2.4)
V2P7: WirelessDMM_PWR (C65.1 U24.1), WirelessDMM_AFE (15 pins)
V3P0: WirelessDMM_PWR (C24.1 U7.1), WirelessDMM_MCU (6 pins)
VRF: WirelessDMM_PWR (C63.1 D1.1 D2.1), WirelessDMM_MCU (8 pins)
ADS8881_CNVST: WirelessDMM_MCU (U10.14), WirelessDMM_AFE (TP4.1 U1.6)
ADS8881_MISO: WirelessDMM_MCU (U10.11), WirelessDMM_AFE (TP3.1 U1.7)
ADS8881_MOSI: WirelessDMM_MCU (U10.10), WirelessDMM_AFE (TP1.1 U1.9)
ADS8881_SCLK: WirelessDMM_MCU (U10.12), WirelessDMM_AFE (TP2.1 U1.8)
AFE_IRNG-SEL: WirelessDMM_MCU (U10.17), WirelessDMM_AFE (TP6.1 U8.4 U8.8)
AFE_RIN-SEL: WirelessDMM_MCU (U10.19), WirelessDMM_AFE (S2.5)
AFE_VI-SEL: WirelessDMM_MCU (U10.18), WirelessDMM_AFE (S1.2)
AFE_VRNG-SEL0: WirelessDMM_MCU (U10.16), WirelessDMM_AFE (U4.6)
AFE_VRNG-SEL1: WirelessDMM_MCU (U10.15), WirelessDMM_AFE (U4.5)
BQ27426_GPIO: WirelessDMM_PWR (R43.1 U19.A1), WirelessDMM_MCU (U10.29)
BQ27426_SCL: WirelessDMM_PWR (R41.1 U19.A3), WirelessDMM_MCU (U10.27)
BQ27426_SDA: WirelessDMM_PWR (R42.1 U19.A2), WirelessDMM_MCU (U10.28)
CAP02: WirelessDMM_MCU (R26.1 TP7.1), WirelessDMM_AFE (R28.2)
CAP12: WirelessDMM_MCU (R27.1 TP8.1), WirelessDMM_AFE (R31.2)
I-SEL: WirelessDMM_MCU (U10.32), WirelessDMM_AFE (U25.4)
PWR_DCDC1-EN: WirelessDMM_PWR (TP9.1 U23.12), WirelessDMM_MCU (U10.30)
PWR_LDO1-EN: WirelessDMM_PWR (TP10.1 U24.4), WirelessDMM_MCU (U10.31)
RF430_ANT1: WirelessDMM_PWR (D1.2), WirelessDMM_MCU (C49.1 C50.1 J4.2 U14.1)
RF430_ANT2: WirelessDMM_PWR (D2.2), WirelessDMM_MCU (C49.2 C50.2 J4.3 U14.2)

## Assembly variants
001: not fitted C18 C19 C37 C44 C45 C50 C69 C70 FID1 FID2 FID3 FID4 FID5 FID6 R29 R59 R61 R62 R64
